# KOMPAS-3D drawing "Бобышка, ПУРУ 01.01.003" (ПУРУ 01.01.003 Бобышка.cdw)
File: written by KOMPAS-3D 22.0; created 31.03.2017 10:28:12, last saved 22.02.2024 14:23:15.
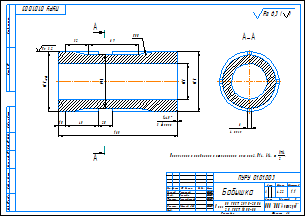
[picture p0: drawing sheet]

Sheet 1: A3, landscape

Document properties: Масса: 0; Автор: cons; Знак неуказанной шероховатости: 4; Параметр неуказанной шероховатости: Ra 6,3; Полное имя файла: ..\ПУРУ 01.01.003 Бобышка.m3d

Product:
- Part/product: Бобышка  | designation ПУРУ 01.01.003
    Материал: Круг$d85 ГОСТ 2590-2006;20 ГОСТ 1050-88$ (density 7859 kg/m3)
    Масса: 4.2181
    Раздел спецификации: Детали
    Форматы листов документа: A3
- Part/product: (unnamed)  | designation 1
- Part/product: (unnamed)  | designation 2
- Part/product: (unnamed)  | designation 3

Title block, sheet 1: Наименование: Бобышка; designation: ПУРУ 01.01.003; Материал: Круг 85 ГОСТ 2590-2006 20 ГОСТ 1050-88; Масса: 4,22; Количество листов документа: 1; organisation: ООО "НПЦ"Антиград"; Форматы листов документа: A3; Литера: А; stored path: D:\РУ 00.00.000 Установка противоградовая ручная\РУ 01.00.000 Стойка\РУ 01.01.000 Ось\Чертежи\РУ 01.0.003 Бобышка.cdw; Разработал: Грицунов; Проверил: Налоева; Т. контр.: Семеновский; Н. контр.: Абшаев А.М.; Разработал, date: 03.04.2017; Проверил, date: 03.04.2017; Т. контр., date: 03.04.2017; Н. контр., date: 03.04.2017

Views: Вид 1, Местный разрез 1, Спереди, Разрез А-А
Referenced files in D:\Град\ПУРУ 00.00.000 Установка пусковая ручная Элия-Р\ПУРУ 01.00.000 Стойка\ПУРУ 01.01.000 Ось\: ПУРУ 01.01.003 Бобышка.m3d
Referenced files in D:\Вован\Антиград\Град\ПУРУ 00.00.000 Установка пусковая ручная Элия-Р\ПУРУ 01.00.000 Стойка\ПУРУ 01.01.000 Ось\: ПУРУ 01.01.003 Бобышка.m3d
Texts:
  Ra 3,2
  Ra 6,3
  Ra 6,3 ( )
  ПУРУ 01.01.003 Бобышка
Dimensions and other numbers on the sheet: 83; 50; 82; 10; 20; 45; 165; 1; 3 фаски; 32; 69; 74; 6; 4 паза; 3; 1:1; 4,22; 03.04.2017

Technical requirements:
  Неуказанные предельные отклонения размеров: H14, h14,    IT14 2 .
